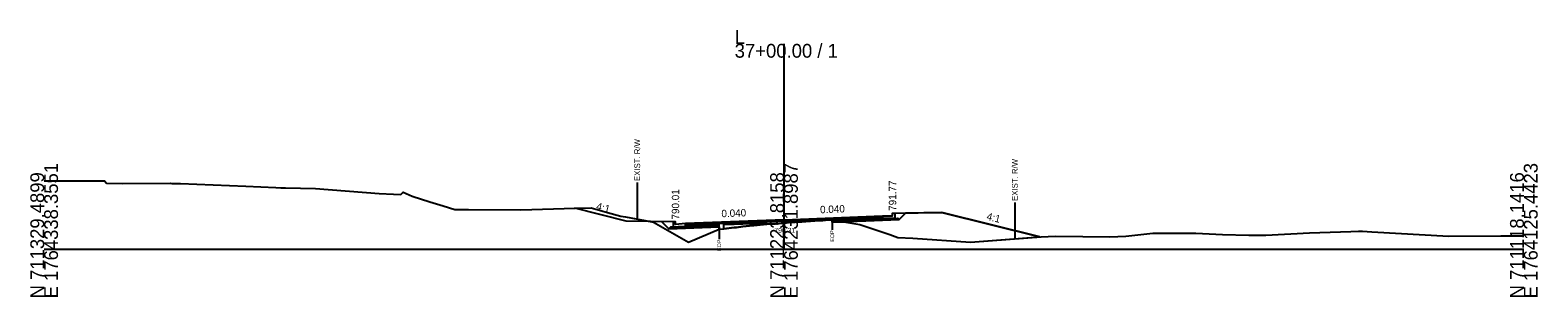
# Model space of a CAD drawing. Extents: x -26 to 5303, y -10 to 9578.
# Drawn here: x 1997.2 to 2302.8, y 6990.3 to 7044.4 of the extents above; entities that cross this region are included whole.
import ezdxf

# ---------------------------------------------------------------- set-up
doc = ezdxf.new("R2010")
doc.units = 0
for name, color, linetype in [('Default', 7, 'Continuous'), ('Exist CMT Pavement', 7, 'Continuous'), ('Exist Cross Section Cell', 7, 'Continuous'), ('Exist XS Ground Line', 7, 'Continuous'), ('Old_Level_10', 7, 'Continuous'), ('Old_Level_3', 7, 'Continuous'), ('Prop CMT Conc Surface', 7, 'Continuous'), ('Prop CMT Concrete Structures', 7, 'Continuous'), ('Prop CMT Pvmt Course 1', 7, 'Continuous'), ('Prop CMT Pvmt Course 1 CG', 7, 'Continuous'), ('Prop CMT Pvmt Course 2', 7, 'Continuous'), ('Prop CMT Pvmt Course 3', 7, 'Continuous'), ('Prop CMT Pvmt Surface', 7, 'Continuous'), ('Prop CMT Slope Grass', 7, 'Continuous'), ('Prop CMT Subgrade Earthwork', 7, 'Continuous'), ('Prop XS Earthwork Shape', 7, 'Continuous'), ('Prop XS Hydro Elevations', 7, 'Continuous'), ('Prop XS SE Text', 7, 'Continuous'), ('Prop XS Side Slope Text', 7, 'Continuous'), ('Prop XS Wedging', 7, 'Continuous')]:
    doc.layers.add(name, color=color, linetype=linetype)

msp = doc.modelspace()

# ---------------------------------------------------------------- linework, layer by layer
at = {"layer": 'Exist CMT Pavement'}
msp.add_lwpolyline([(2136.86, 7004.07), (2137.81, 7004.13), (2139.9, 7004.36), (2140.35, 7004.41), (2141.67, 7004.57), (2143, 7004.7), (2143.87, 7004.78), (2146.54, 7005.05), (2147.12, 7005.1), (2147.7, 7005.14), (2148.26, 7005.16), (2150.51, 7005.35), (2150.91, 7005.38), (2152.27, 7005.47), (2153.64, 7005.56), (2154.44, 7005.62), (2155.81, 7005.71), (2157.19, 7005.8), (2157.58, 7005.82), (2157.9, 7005.84), (2158.98, 7005.91), (2159.77, 7005.96)], dxfattribs=at)
at = {"layer": 'Exist Cross Section Cell'}
for p, q in [((2150, 7000), (2150, 7041.65)), ((2000, 7000), (2150, 7000)), ((2150, 7000), (2300, 7000))]:
    msp.add_line(p, q, dxfattribs=at)
at = {"layer": 'Exist XS Ground Line'}
msp.add_lwpolyline([(2000, 7013.88), (2001.25, 7013.88), (2012.24, 7013.88), (2012.67, 7013.38), (2015.84, 7013.32), (2025.58, 7013.37), (2025.9, 7013.35), (2026.53, 7013.34), (2027.66, 7013.3), (2040.89, 7012.79), (2046.97, 7012.51), (2047.96, 7012.47), (2048.96, 7012.44), (2055.03, 7012.28), (2067.94, 7011.3), (2070.81, 7011.15), (2072.31, 7011.08), (2072.81, 7011.58), (2074.6, 7010.76), (2078.22, 7009.6), (2080.88, 7008.77), (2083.24, 7008.07), (2086.05, 7008.04), (2096.67, 7007.99), (2107.63, 7008.3), (2110.92, 7008.36), (2114.19, 7007.46), (2116.92, 7006.71), (2117.84, 7006.58), (2123.51, 7005.48), (2130.63, 7001.41), (2136.86, 7004.07), (2137.81, 7004.13), (2139.9, 7004.36), (2140.35, 7004.41), (2141.67, 7004.57), (2143, 7004.7), (2143.87, 7004.78), (2146.54, 7005.05), (2147.12, 7005.1), (2148.26, 7005.16), (2150.51, 7005.35), (2150.91, 7005.38), (2153.64, 7005.56), (2154.44, 7005.62), (2157.19, 7005.8), (2157.58, 7005.82), (2157.9, 7005.84), (2158.98, 7005.91), (2159.77, 7005.96), (2163.77, 7005.24), (2165.36, 7005), (2168.81, 7003.82), (2171.46, 7002.97), (2173.06, 7002.34), (2176.11, 7002.2), (2187.82, 7001.38), (2202.12, 7002.51), (2203.54, 7002.57), (2205.12, 7002.62), (2216.07, 7002.5), (2219.31, 7002.64), (2224.76, 7003.21), (2230.16, 7003.26), (2231.83, 7003.27), (2233.51, 7003.23), (2238.9, 7002.96), (2244.26, 7002.83), (2247.71, 7002.83), (2256.55, 7003.28), (2264.9, 7003.6), (2266.51, 7003.66), (2267.28, 7003.65), (2269.18, 7003.53), (2284.79, 7002.65), (2295.35, 7002.72), (2300, 7002.69)], dxfattribs=at)
at = {"layer": 'Old_Level_10'}
for p, q in [((2120.24, 7013.52), (2120.24, 7006.12)), ((2196.8, 7009.49), (2196.8, 7002.09)), ((2136.86, 7004.07), (2136.86, 7002.01)), ((2159.77, 7005.96), (2159.77, 7003.91))]:
    msp.add_line(p, q, dxfattribs=at)
at = {"layer": 'Prop CMT Conc Surface'}
for points in [[(2170, 7006.77), (2172, 7006.77)], [(2172, 7006.77), (2172, 7007.27), (2172.5, 7007.27)], [(2128, 7005.01), (2128, 7005.51), (2127.5, 7005.51)], [(2130, 7005.17), (2128, 7005.01)]]:
    msp.add_lwpolyline(points, dxfattribs=at)
at = {"layer": 'Prop CMT Concrete Structures'}
for points in [[(2170, 7006.77), (2172, 7006.77), (2172, 7007.27), (2172.5, 7007.27)], [(2172.5, 7007.27), (2172.5, 7006.29), (2170, 7006.19)], [(2170, 7006.19), (2170, 7006.77)], [(2130, 7005.17), (2128, 7005.01), (2128, 7005.51), (2127.5, 7005.51)], [(2127.5, 7005.51), (2127.5, 7004.49), (2130, 7004.59)], [(2130, 7004.59), (2130, 7005.17)]]:
    msp.add_lwpolyline(points, dxfattribs=at)
at = {"layer": 'Prop CMT Pvmt Course 1'}
for points in [[(2150, 7005.97), (2170, 7006.77)], [(2170, 7006.52), (2159.77, 7006.11)], [(2170, 7006.77), (2170, 7006.52)], [(2150, 7005.97), (2130, 7005.17)], [(2130, 7004.92), (2136.86, 7005.19)], [(2130, 7005.17), (2130, 7004.92)], [(2136.86, 7005.19), (2150, 7005.72)], [(2136.86, 7005.19), (2136.86, 7005.19)], [(2159.77, 7006.11), (2150, 7005.72)], [(2150, 7005.72), (2150, 7005.97)], [(2150, 7005.72), (2150, 7005.72), (2150, 7005.72)], [(2159.77, 7006.11), (2159.77, 7006.11)]]:
    msp.add_lwpolyline(points, dxfattribs=at)
at = {"layer": 'Prop CMT Pvmt Course 1 CG'}
for points in [[(2170, 7006.19), (2173, 7006.31), (2173.32, 7005.99)], [(2130, 7004.59), (2127, 7004.47), (2126.65, 7004.12)], [(2126.65, 7004.12), (2130, 7004.25)], [(2130, 7004.25), (2130, 7004.59)], [(2170, 7005.85), (2170, 7006.19)], [(2173.32, 7005.99), (2170, 7005.85)]]:
    msp.add_lwpolyline(points, dxfattribs=at)
at = {"layer": 'Prop CMT Pvmt Course 2'}
for points in [[(2159.77, 7006.11), (2170, 7006.52)], [(2170, 7006.52), (2170, 7006.19)], [(2136.86, 7005.19), (2130, 7004.92)], [(2130, 7004.92), (2130, 7004.59)], [(2130, 7004.59), (2136.86, 7004.86)], [(2136.86, 7004.86), (2136.86, 7005.19)], [(2170, 7006.19), (2159.77, 7005.78)], [(2159.77, 7005.78), (2159.77, 7006.11)]]:
    msp.add_lwpolyline(points, dxfattribs=at)
at = {"layer": 'Prop CMT Pvmt Course 3'}
for points in [[(2136.86, 7004.86), (2130, 7004.59)], [(2130, 7004.59), (2130, 7004.25)], [(2130, 7004.25), (2136.86, 7004.53)], [(2136.86, 7004.53), (2136.86, 7004.86)], [(2159.77, 7005.78), (2170, 7006.19)], [(2170, 7005.85), (2159.77, 7005.44)], [(2159.77, 7005.44), (2159.77, 7005.78)], [(2170, 7006.19), (2170, 7005.85)]]:
    msp.add_lwpolyline(points, dxfattribs=at)
at = {"layer": 'Prop CMT Pvmt Surface'}
for points in [[(2150, 7005.97), (2170, 7006.77)], [(2150, 7005.97), (2130, 7005.17)]]:
    msp.add_lwpolyline(points, dxfattribs=at)
at = {"layer": 'Prop CMT Slope Grass'}
for points in [[(2127.5, 7005.51), (2118, 7005.7), (2107.59, 7008.3)], [(2172.5, 7007.27), (2182, 7007.46), (2201.88, 7002.49)]]:
    msp.add_lwpolyline(points, dxfattribs=at)
at = {"layer": 'Prop CMT Subgrade Earthwork'}
for p, q in [((2136.86, 7004.53), (2136.86, 7004.07)), ((2159.77, 7005.44), (2159.77, 7005.96))]:
    msp.add_line(p, q, dxfattribs=at)
for points in [[(2170, 7005.85), (2173.32, 7005.99), (2174.65, 7007.31)], [(2130, 7004.25), (2126.65, 7004.12), (2125.22, 7005.55)], [(2136.86, 7004.53), (2130, 7004.25)], [(2159.77, 7005.44), (2170, 7005.85)]]:
    msp.add_lwpolyline(points, dxfattribs=at)
at = {"layer": 'Prop XS Earthwork Shape'}
for points in [[(2107.63, 7008.3), (2110.92, 7008.36), (2114.19, 7007.46), (2116.92, 7006.71), (2117.84, 7006.58), (2122.9, 7005.6), (2118, 7005.7), (2107.59, 7008.3)], [(2176.11, 7002.2), (2187.82, 7001.38), (2201.88, 7002.49), (2182, 7007.46), (2174.65, 7007.31), (2173.32, 7005.99), (2170, 7005.85), (2162.12, 7005.54), (2163.77, 7005.24), (2165.36, 7005), (2168.81, 7003.82), (2171.46, 7002.97), (2173.06, 7002.34)], [(2123.51, 7005.48), (2130.63, 7001.41), (2136.86, 7004.07), (2136.86, 7004.53), (2130, 7004.25), (2126.65, 7004.12), (2125.22, 7005.55), (2122.9, 7005.6)], [(2126.65, 7004.12), (2125.22, 7005.55), (2122.9, 7005.6), (2123.51, 7005.48), (2130.63, 7001.41), (2136.86, 7004.07), (2136.86, 7004.53), (2130, 7004.25)], [(2159.77, 7005.44), (2162.12, 7005.54), (2159.77, 7005.96)]]:
    msp.add_lwpolyline(points, close=True, dxfattribs=at)
at = {"layer": 'Prop XS Wedging'}
for points in [[(2137.81, 7004.13), (2137.81, 7005.35), (2139.9, 7005.42), (2140.35, 7005.43), (2141.67, 7005.47), (2143, 7005.51), (2143.87, 7005.54), (2146.55, 7005.62), (2147.12, 7005.63), (2147.7, 7005.65), (2148.26, 7005.67), (2150, 7005.72), (2150.51, 7005.73), (2150.91, 7005.75), (2152.27, 7005.79), (2153.64, 7005.83), (2154.44, 7005.85), (2155.81, 7005.89), (2157.19, 7005.93), (2157.58, 7005.95), (2157.9, 7005.96), (2158.99, 7005.99), (2159.78, 7006.01), (2159.78, 7005.96), (2158.99, 7005.91), (2157.9, 7005.84), (2157.58, 7005.82), (2157.19, 7005.8), (2155.81, 7005.71), (2154.44, 7005.62), (2153.64, 7005.56), (2152.27, 7005.47), (2150.91, 7005.38), (2150.51, 7005.35), (2150, 7005.31), (2148.26, 7005.16), (2147.7, 7005.14), (2147.12, 7005.1), (2146.55, 7005.05), (2143.87, 7004.78), (2143, 7004.7), (2141.67, 7004.57), (2140.35, 7004.41), (2139.9, 7004.36)], [(2137.81, 7004.13), (2137.81, 7005.35), (2139.9, 7005.42), (2140.35, 7005.43), (2141.67, 7005.47), (2143, 7005.51), (2143.87, 7005.54), (2146.55, 7005.62), (2147.12, 7005.63), (2147.7, 7005.65), (2148.26, 7005.67), (2150, 7005.72), (2150.51, 7005.73), (2150.91, 7005.75), (2152.27, 7005.79), (2153.64, 7005.83), (2154.44, 7005.85), (2155.09, 7005.87), (2155.29, 7005.68), (2154.44, 7005.62), (2153.64, 7005.56), (2152.27, 7005.47), (2150.91, 7005.38), (2150.51, 7005.35), (2150, 7005.31), (2148.26, 7005.16), (2147.7, 7005.14), (2147.12, 7005.1), (2146.55, 7005.05), (2143.87, 7004.78), (2143, 7004.7), (2141.67, 7004.57), (2140.35, 7004.41), (2139.9, 7004.36)], [(2137.81, 7004.13), (2137.81, 7005.02), (2139.9, 7005.09), (2140.35, 7005.1), (2141.67, 7005.14), (2143, 7005.18), (2143.87, 7005.21), (2146.41, 7005.28), (2146.63, 7005.05), (2143.87, 7004.78), (2143, 7004.7), (2141.67, 7004.57), (2140.35, 7004.41), (2139.9, 7004.36)]]:
    msp.add_lwpolyline(points, close=True, dxfattribs=at)

# ---------------------------------------------------------------- texts
at = {"layer": 'Default'}
msp.add_text('-', height=0.0001, dxfattribs=at).set_placement((2000, 7000))
at = {"layer": 'Exist Cross Section Cell'}
for s, p in [('L', (2140, 7041.65)), ('37+00.00 / 1', (2140, 7038.85))]:
    msp.add_text(s, height=2.8, dxfattribs=at).set_placement(p)
for s, p in [('N 711329.4899', (2000, 6990)), ('E 1764338.3551', (2002.8, 6990)), ('N 711223.8158', (2150, 6990)), ('E 1764231.8987', (2152.8, 6990)), ('N 711118.1416', (2300, 6990)), ('E 1764125.4423', (2302.8, 6990))]:
    msp.add_text(s, height=2.8, rotation=90, dxfattribs=at).set_placement(p)
at = {"layer": 'Old_Level_10'}
for s, height, p in [('EXIST. R/W', 1.181, (2120.83, 7013.82)), ('EXIST. R/W', 1.181, (2197.39, 7009.79)), ('EOP', 0.787, (2160.17, 7001.51)), ('EOP', 0.787, (2137.25, 6999.62))]:
    msp.add_text(s, height=height, rotation=90, dxfattribs=at).set_placement(p)
at = {"layer": 'Old_Level_3'}
msp.add_text('790.31', height=1, dxfattribs=at).set_placement((2148.05, 7003.31))
at = {"layer": 'Prop XS Hydro Elevations'}
for s, p in [('791.77', (2172.75, 7007.77)), ('790.01', (2128.75, 7006.01))]:
    msp.add_text(s, height=1.5, rotation=90, dxfattribs=at).set_placement(p)
at = {"layer": 'Prop XS SE Text'}
for p in [(2137.34, 7006.46), (2157.34, 7007.26)]:
    msp.add_text('0.040', height=1.5, rotation=2.2906, dxfattribs=at).set_placement(p)
at = {"layer": 'Prop XS Side Slope Text'}
for p in [(2111.82, 7008.02), (2190.97, 7005.99)]:
    msp.add_text('4:1', height=1.5, rotation=345.9638, dxfattribs=at).set_placement(p)

doc.saveas('drawing.dxf')
